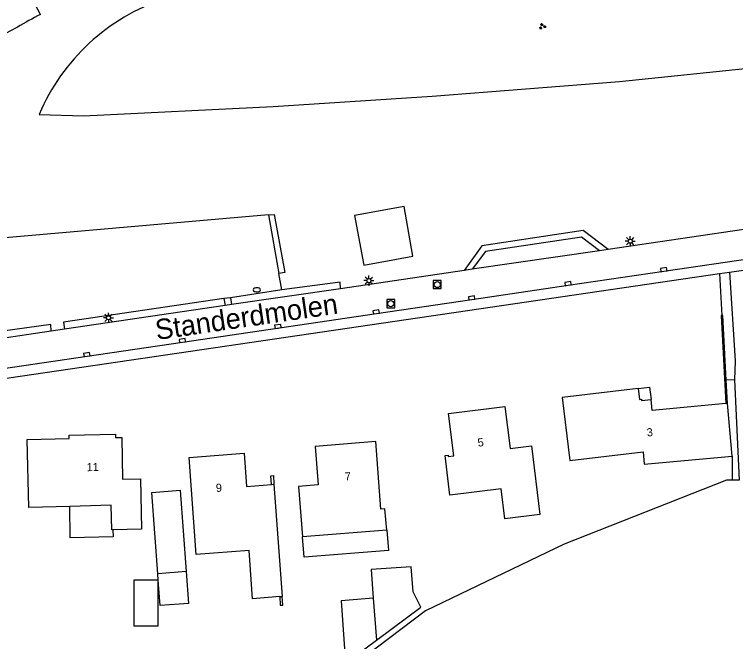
# Model space of a CAD drawing. Extents: x 136000 to 141000, y 400494 to 402006.
# Drawn here: x 137824.5 to 137913.3, y 400612.9 to 400690.1 of the extents above; entities that cross this region are included whole.
import ezdxf

# ---------------------------------------------------------------- set-up
doc = ezdxf.new("R2010")
doc.units = 0
for name, color, linetype in [('gg-afsc-hekwerk', 7, 'Continuous'), ('gg-afsc-muur', 7, 'Continuous'), ('gg-anno-huisnummerreeks BGT', 7, 'Continuous'), ('gg-anno-openbare ruimte label', 7, 'Continuous'), ('gg-bbg-bijgebouw', 7, 'Continuous'), ('gg-bbg-gedigitaliseerde bijgebouw', 7, 'Continuous'), ('gg-bbg-hoofdgebouw', 7, 'Continuous'), ('gg-bbg-luifel en loopbrug', 7, 'Continuous'), ('gg-bbg-onder overbouw', 7, 'Continuous'), ('gg-bbg-pand overbouw', 7, 'Continuous'), ('gg-knt-verharding', 7, 'Continuous'), ('gg-knt-verharding nz', 7, 'Continuous'), ('gg-kwrk-keermuur', 7, 'Continuous'), ('gt-grn-groengrens', 7, 'Continuous'), ('gt-grn-weggrens', 7, 'Continuous'), ('gt-symb-brandkraan', 7, 'Continuous'), ('gt-symb-groenvak', 7, 'Continuous'), ('gt-symb-kolk', 7, 'Continuous'), ('gt-symb-lichtmast', 7, 'Continuous'), ('gt-symb-rioolschacht', 7, 'Continuous')]:
    doc.layers.add(name, color=color, linetype=linetype)

# ---------------------------------------------------------------- blocks, each defined once
blk = doc.blocks.new('gt0-GRVAK')
at = {"layer": 'gt-symb-groenvak'}
for p, q in [((-0.11, 0.189), (-0.228, 0.24)), ((-0.182, 0.153), (0.088, 0.153)), ((-0.091, 0.211), (-0.156, 0.322)), ((-0.047, 0.214), (-0.047, 0.393)), ((-0.004, 0.211), (0.061, 0.322)), ((0.015, 0.189), (0.133, 0.24)), ((0.262, -0.052), (0.197, 0.059)), ((0.305, -0.049), (0.305, 0.13)), ((0.349, -0.052), (0.414, 0.059)), ((-0.245, -0.228), (-0.363, -0.177)), ((-0.318, -0.264), (-0.047, -0.264)), ((-0.226, -0.206), (-0.291, -0.095)), ((-0.183, -0.203), (-0.183, -0.024)), ((-0.139, -0.206), (-0.074, -0.095)), ((-0.12, -0.228), (-0.002, -0.177)), ((0.243, -0.074), (0.125, -0.023)), ((0.17, -0.11), (0.441, -0.11)), ((0.368, -0.074), (0.486, -0.023))]:
    blk.add_line(p, q, dxfattribs=at)
blk = doc.blocks.new('gt0-KOLK')
at = {"layer": 'gt-symb-kolk'}
blk.add_lwpolyline([(0, 0), (0.375, 0), (0.375, 0.4), (-0.375, 0.4), (-0.375, 0), (0, 0)], dxfattribs=at)
blk = doc.blocks.new('gt0-RS')
at = {"layer": 'gt-symb-rioolschacht'}
blk.add_lwpolyline([(-0.5, -0.5), (0.5, -0.5), (0.5, 0.5), (-0.5, 0.5)], close=True, dxfattribs=at)
blk.add_circle((0, 0), 0.375, dxfattribs=at)
blk = doc.blocks.new('gt0-LMAST')
at = {"layer": 'gt-symb-lichtmast'}
for p, q in [((-0.182, 0.173), (-0.447, 0.438)), ((-0.005, 0.246), (-0.005, 0.621)), ((0.172, 0.173), (0.437, 0.438)), ((-0.255, -0.004), (-0.63, -0.004)), ((-0.182, -0.181), (-0.447, -0.446)), ((-0.005, -0.254), (-0.005, -0.629)), ((0.437, -0.446), (0.172, -0.181)), ((0.245, -0.004), (0.62, -0.004))]:
    blk.add_line(p, q, dxfattribs=at)
blk.add_circle((-0.005, -0.004), 0.25, dxfattribs=at)
blk = doc.blocks.new('gt0-BR')
at = {"layer": 'gt-symb-brandkraan'}
for centre, radius, start, end in [((-0.244, 0), 0.206, 107.56694, 252.43307), ((0.599, -2.664), 3, 106.89205, 107.56694), ((0, -0.691), 0.938, 73.10799, 106.89205), ((-0.599, -2.664), 3, 72.43309, 73.10799), ((0.244, 0), 0.206, 287.56695, 72.43309), ((0.599, 2.664), 3, 252.43307, 253.10797), ((0, 0.691), 0.938, 253.10797, 286.89206), ((-0.599, 2.664), 3, 286.89206, 287.56695)]:
    blk.add_arc(centre, radius, start, end, dxfattribs=at)

msp = doc.modelspace()

# ---------------------------------------------------------------- linework, layer by layer
at = {"layer": 'gg-afsc-hekwerk'}
msp.add_line((137913.732, 400632.784), (137912.903, 400632.784), dxfattribs=at)
msp.add_lwpolyline([(137912.903, 400632.784), (137912.184, 400632.784), (137892.211, 400624.885), (137875.114, 400616.678), (137860.247, 400605.425)], dxfattribs=at)
at = {"layer": 'gg-afsc-muur'}
for points in [[(137856.134, 400632.252), (137856.068, 400633.316), (137856.371, 400633.338), (137856.448, 400632.276)], [(137857.15, 400618.448), (137857.229, 400617.373), (137857.53, 400617.395), (137857.452, 400618.472)]]:
    msp.add_lwpolyline(points, dxfattribs=at)
at = {"layer": 'gg-bbg-bijgebouw'}
for p, q in [((137842.134, 400621.255), (137841.4, 400631.282)), ((137845.639, 400621.524), (137842.134, 400621.255)), ((137868.686, 400618.246), (137869.092, 400613.081))]:
    msp.add_line(p, q, dxfattribs=at)
for points in [[(137841.4, 400631.282), (137844.905, 400631.552), (137845.639, 400621.524)], [(137869.092, 400613.081), (137874.555, 400617.142), (137873.59, 400619.016), (137873.367, 400622.089), (137868.409, 400621.767), (137868.686, 400618.246)]]:
    msp.add_lwpolyline(points, dxfattribs=at)
at = {"layer": 'gg-bbg-gedigitaliseerde bijgebouw'}
msp.add_lwpolyline([(137842.193, 400620.452), (137839.17, 400620.452), (137839.17, 400614.855), (137842.193, 400614.855), (137842.193, 400620.452)], dxfattribs=at)
at = {"layer": 'gg-bbg-hoofdgebouw'}
for p, q in [((137912.302, 400642.228), (137912.123, 400642.211)), ((137912.903, 400635.738), (137912.302, 400642.228)), ((137856.134, 400632.252), (137856.448, 400632.276)), ((137856.448, 400632.276), (137857.452, 400618.472)), ((137870.334, 400626.644), (137859.96, 400625.798)), ((137857.15, 400618.448), (137857.452, 400618.472))]:
    msp.add_line(p, q, dxfattribs=at)
for points in [[(137901.309, 400644.076), (137891.962, 400642.976), (137892.877, 400635.2), (137901.915, 400636.263), (137902.057, 400634.733), (137912.903, 400635.738)], [(137912.123, 400642.211), (137903.047, 400641.371), (137902.895, 400642.728)], [(137877.519, 400635.836), (137877.887, 400635.875), (137877.909, 400635.694), (137878.582, 400635.776), (137877.951, 400640.977), (137884.884, 400641.845), (137885.531, 400636.674), (137888.148, 400637.001), (137889.19, 400628.547), (137884.891, 400628.015), (137884.436, 400631.711), (137878.125, 400630.921), (137877.519, 400635.836)], [(137826.032, 400637.778), (137831.218, 400637.911), (137831.219, 400638.343), (137836.928, 400638.459), (137836.937, 400638.03), (137837.697, 400638.045), (137837.802, 400632.896), (137839.992, 400632.941), (137840.118, 400626.742), (137836.604, 400626.67)], [(137831.284, 400629.558), (137826.25, 400629.427), (137826.032, 400637.778)], [(137870.334, 400626.644), (137870.115, 400629.241), (137869.614, 400629.215), (137868.974, 400637.53), (137861.52, 400636.947), (137861.891, 400632.201), (137859.474, 400632.012), (137859.96, 400625.798)], [(137857.15, 400618.448), (137853.813, 400618.183), (137853.379, 400624.104), (137846.868, 400623.636), (137845.999, 400635.589), (137852.772, 400636.088), (137853.074, 400632.021), (137856.134, 400632.252)], [(137836.604, 400626.67), (137836.489, 400626.668), (137836.41, 400629.692), (137831.284, 400629.558)]]:
    msp.add_lwpolyline(points, dxfattribs=at)
at = {"layer": 'gg-bbg-luifel en loopbrug'}
msp.add_line((137842.193, 400620.452), (137842.134, 400621.255), dxfattribs=at)
for points in [[(137836.604, 400626.67), (137836.622, 400625.786), (137831.363, 400625.679), (137831.284, 400629.558)], [(137870.334, 400626.644), (137870.548, 400624.107), (137860.156, 400623.29), (137859.96, 400625.798)], [(137845.639, 400621.524), (137845.926, 400617.603), (137842.42, 400617.347), (137842.193, 400620.452)], [(137868.686, 400618.246), (137864.709, 400617.94), (137865.278, 400610.246), (137869.092, 400613.081)]]:
    msp.add_lwpolyline(points, dxfattribs=at)
at = {"layer": 'gg-bbg-onder overbouw'}
msp.add_lwpolyline([(137901.309, 400644.076), (137901.479, 400642.709), (137901.698, 400642.741), (137901.719, 400642.596), (137902.895, 400642.728)], dxfattribs=at)
at = {"layer": 'gg-bbg-pand overbouw'}
msp.add_lwpolyline([(137901.309, 400644.076), (137902.717, 400644.242), (137902.895, 400642.728)], dxfattribs=at)
at = {"layer": 'gg-knt-verharding'}
for p, q in [((137935.61, 400666.787), (137897.598, 400661.195)), ((137912.547, 400658.395), (137940.8, 400662.555)), ((137897.598, 400661.195), (137896.547, 400661.04)), ((137802.6, 400642.275), (137911.341, 400658.226)), ((137879.864, 400658.606), (137864.659, 400656.358)), ((137880.857, 400658.763), (137879.864, 400658.606)), ((137911.341, 400658.226), (137912.547, 400658.395)), ((137911.341, 400658.226), (137911.628, 400653.059)), ((137864.659, 400656.358), (137851.228, 400654.398)), ((137850.418, 400654.279), (137830.649, 400651.394)), ((137851.228, 400654.398), (137850.418, 400654.279)), ((137829.009, 400651.137), (137819.324, 400649.706)), ((137830.649, 400651.394), (137829.009, 400651.137))]:
    msp.add_line(p, q, dxfattribs=at)
for points in [[(137873.559, 400660.354), (137872.49, 400666.476), (137866.383, 400665.373), (137867.497, 400659.276), (137873.559, 400660.354)], [(137897.598, 400661.195), (137894.515, 400663.529), (137882.071, 400661.655), (137879.864, 400658.606)], [(137896.547, 400661.04), (137894.307, 400662.708), (137882.522, 400660.962), (137880.857, 400658.763)]]:
    msp.add_lwpolyline(points, dxfattribs=at)
for centre, radius, start, end in [((137857.956, 400630.972), 71.517, 117.42687, 134.32848), ((137857.125, 400633.181), 64.122, 117.33692, 120.21611), ((137852.779, 400636.755), 58.879, 118.3118, 151.848)]:
    msp.add_arc(centre, radius, start, end, dxfattribs=at)
at = {"layer": 'gg-knt-verharding nz'}
msp.add_line((137896.547, 400661.04), (137880.857, 400658.763), dxfattribs=at)
msp.add_lwpolyline([(137802.057, 400643.39), (137809.708, 400644.559), (137833.426, 400648.056), (137845.19, 400649.778), (137869.066, 400653.303), (137880.824, 400655.027), (137892.688, 400656.785), (137904.488, 400658.513), (137916.514, 400660.286), (137927.955, 400661.987), (137936.149, 400663.188)], dxfattribs=at)
at = {"layer": 'gg-kwrk-keermuur'}
msp.add_line((137912.302, 400642.228), (137912.147, 400645.098), dxfattribs=at)
for points in [[(137911.628, 400653.059), (137911.538, 400653.054), (137912.123, 400642.211)], [(137912.147, 400645.098), (137911.718, 400653.063), (137911.628, 400653.059)]]:
    msp.add_lwpolyline(points, dxfattribs=at)
at = {"layer": 'gt-grn-groengrens'}
for p, q in [((137855.768, 400665.443), (137821.464, 400662.481)), ((137855.768, 400665.443), (137857.061, 400658.251)), ((137857.411, 400656.221), (137857.061, 400658.251)), ((137857.411, 400656.221), (137851.105, 400655.24)), ((137851.105, 400655.24), (137850.291, 400655.154)), ((137850.291, 400655.154), (137850.418, 400654.279)), ((137851.105, 400655.24), (137851.228, 400654.398)), ((137913.171, 400645.153), (137912.147, 400645.098)), ((137913.171, 400645.153), (137913.732, 400632.784)), ((137912.903, 400635.738), (137912.903, 400632.784))]:
    msp.add_line(p, q, dxfattribs=at)
for points in [[(137827.535, 400677.831), (137832.98, 400677.658), (137856.365, 400678.791), (137875.952, 400680.065), (137899.022, 400681.87), (137936.711, 400685.789), (137937.984, 400688.887)], [(137855.768, 400665.443), (137856.488, 400665.512), (137857.775, 400658.368), (137857.061, 400658.251)], [(137912.547, 400658.395), (137913.255, 400647.477), (137913.171, 400645.153)], [(137864.659, 400656.358), (137864.584, 400657.169), (137857.411, 400656.221)], [(137850.291, 400655.154), (137830.511, 400652.222), (137830.649, 400651.394)], [(137829.009, 400651.137), (137828.964, 400651.947), (137823.059, 400651.118)]]:
    msp.add_lwpolyline(points, dxfattribs=at)
msp.add_arc((137850.953, 400667.915), 25.431, 108.47216, 157.04941, dxfattribs=at)
at = {"layer": 'gt-grn-weggrens'}
msp.add_line((137827.679, 400690.142), (137826.679, 400692.106), dxfattribs=at)

# ---------------------------------------------------------------- block references
at = {"layer": 'gt-symb-brandkraan'}
msp.add_blockref('gt0-BR', (137854.35, 400656.224), dxfattribs=at)
at = {"layer": 'gt-symb-groenvak'}
msp.add_blockref('gt0-GRVAK', (137889.503, 400688.667), dxfattribs=at)
at = {"layer": 'gt-symb-kolk'}
for p, rotation in [((137904.488, 400658.513), 8.455351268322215), ((137892.688, 400656.785), 8.455351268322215), ((137880.824, 400655.027), 8.455351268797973), ((137869.066, 400653.303), 8.455351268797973), ((137856.963, 400651.52), 8.455351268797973), ((137845.19, 400649.778), 8.455351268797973), ((137833.426, 400648.056), 8.455351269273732)]:
    msp.add_blockref('gt0-KOLK', p, dxfattribs=dict(at, rotation=rotation))
at = {"layer": 'gt-symb-lichtmast'}
for p in [(137900.335, 400662.214), (137868.143, 400657.359), (137836.075, 400652.786)]:
    msp.add_blockref('gt0-LMAST', p, dxfattribs=at)
at = {"layer": 'gt-symb-rioolschacht'}
for p in [(137876.56, 400656.869), (137870.836, 400654.515)]:
    msp.add_blockref('gt0-RS', p, dxfattribs=at)

# ---------------------------------------------------------------- texts
at = {"layer": 'gg-anno-huisnummerreeks BGT'}
for s, rotation, p in [('3', 6.4, (137902.423, 400638.147)), ('5', 7.1, (137881.591, 400636.898)), ('11', 1.2, (137833.388, 400633.886)), ('7', 4.5, (137865.211, 400632.723)), ('9', 4.2, (137849.329, 400631.322))]:
    msp.add_text(s, height=1, rotation=rotation, dxfattribs=at).set_placement(p)
at = {"layer": 'gg-anno-openbare ruimte label'}
msp.add_text('Standerdmolen', height=2.5, rotation=8.3, dxfattribs=at).set_placement((137842.015, 400650.04))

doc.saveas('drawing.dxf')
